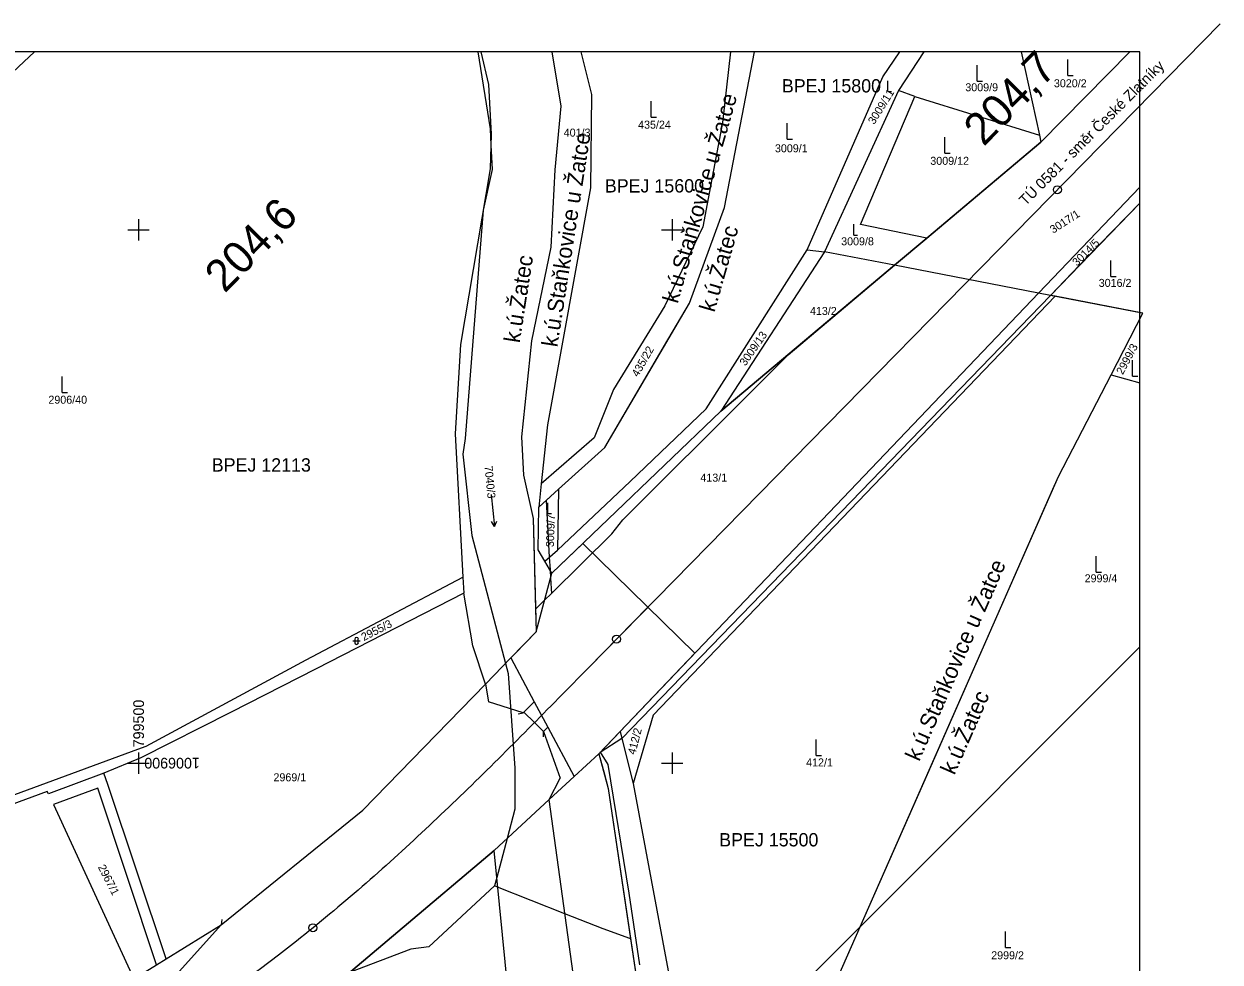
# Model space of a CAD drawing. Extents: x -800194 to -799297, y -1007177 to -1006761.
# Drawn here: x -799521.5 to -799297.3, y -1006937.3 to -1006761.4 of the extents above; entities that cross this region are included whole.
import ezdxf

# ---------------------------------------------------------------- set-up
doc = ezdxf.new("R2010")
doc.units = 0
for name, color, linetype in [('02_Osa_koleje', 7, 'Continuous'), ('_návrh', 7, 'Continuous'), ('_Vrstva 7 - Přesunutá', 7, 'Continuous'), ('BPEJ', 7, 'Continuous'), ('Dočasné zábory', 7, 'Continuous'), ('Legenda 1', 7, 'Continuous'), ('Pozemky SŽDC', 7, 'Continuous'), ('Ramove udaje', 7, 'Continuous'), ('Vrstva 1', 7, 'Continuous'), ('Vrstva 53', 7, 'Continuous'), ('Vrstva 55', 7, 'Continuous'), ('Vrstva 56', 7, 'Continuous'), ('Vrstva 57', 7, 'Continuous'), ('Vrstva 58', 7, 'Continuous'), ('Vrstva 7', 7, 'Continuous')]:
    doc.layers.add(name, color=color, linetype=linetype)

msp = doc.modelspace()

# ---------------------------------------------------------------- linework, layer by layer
at = {"layer": '02_Osa_koleje'}
msp.add_lwpolyline([(-799415.71, -1006882.13), (-799416.41, -1006882.84), (-799417.11, -1006883.55), (-799417.81, -1006884.27), (-799418.51, -1006884.98), (-799419.22, -1006885.7), (-799419.92, -1006886.41), (-799420.62, -1006887.12), (-799421.32, -1006887.84), (-799422.02, -1006888.55), (-799422.72, -1006889.26), (-799423.42, -1006889.97), (-799424.12, -1006890.69), (-799424.83, -1006891.4), (-799425.53, -1006892.11), (-799426.23, -1006892.82), (-799426.94, -1006893.53), (-799427.64, -1006894.24), (-799428.35, -1006894.95), (-799429.05, -1006895.66), (-799429.76, -1006896.36), (-799430.47, -1006897.07), (-799431.17, -1006897.78), (-799431.88, -1006898.48), (-799432.59, -1006899.19), (-799433.3, -1006899.89), (-799434.01, -1006900.6), (-799434.72, -1006901.3), (-799435.44, -1006902), (-799436.15, -1006902.7), (-799436.86, -1006903.4), (-799437.58, -1006904.1), (-799438.29, -1006904.8), (-799439.01, -1006905.5), (-799439.73, -1006906.19), (-799440.45, -1006906.89), (-799441.17, -1006907.58), (-799441.89, -1006908.27), (-799442.61, -1006908.96), (-799443.34, -1006909.65), (-799444.06, -1006910.34), (-799444.79, -1006911.03), (-799445.52, -1006911.72), (-799446.25, -1006912.4), (-799446.98, -1006913.08), (-799447.71, -1006913.77), (-799448.44, -1006914.45), (-799449.18, -1006915.12), (-799449.91, -1006915.8), (-799450.65, -1006916.48), (-799451.39, -1006917.15), (-799452.13, -1006917.82), (-799452.87, -1006918.49), (-799453.61, -1006919.16), (-799454.36, -1006919.83), (-799455.11, -1006920.49), (-799455.85, -1006921.16), (-799456.6, -1006921.82), (-799457.36, -1006922.48), (-799458.11, -1006923.13), (-799458.87, -1006923.79), (-799459.62, -1006924.44), (-799460.38, -1006925.09), (-799461.14, -1006925.74), (-799461.91, -1006926.39), (-799462.67, -1006927.03), (-799463.44, -1006927.68), (-799464.21, -1006928.32), (-799464.98, -1006928.95), (-799465.75, -1006929.59), (-799466.52, -1006930.22), (-799467.3, -1006930.85), (-799468.08, -1006931.48), (-799468.86, -1006932.1), (-799469.64, -1006932.73), (-799470.43, -1006933.35)], dxfattribs=at)
msp.add_arc((-799651.02, -1006703.89), 292, 255.6249, 308.2052, dxfattribs=at)
at = {"layer": '_návrh'}
msp.add_line((-799415.71, -1006882.13), (-799404.56, -1006870.75), dxfattribs=at)
at = {"layer": '_Vrstva 7 - Přesunutá'}
msp.add_circle((-799467.33, -1006930.87), 0.75, dxfattribs=at)
at = {"layer": 'BPEJ'}
msp.add_line((-799329.14, -1006812.3), (-799312.4, -1006795.04), dxfattribs=at)
for points in [[(-799436.44, -1006766.65), (-799434.15, -1006781.08), (-799433.98, -1006784.14), (-799433.73, -1006788.7), (-799435.42, -1006796.33), (-799438.81, -1006839.12), (-799439.24, -1006842.08), (-799437.54, -1006857.33), (-799431.26, -1006881.3), (-799430.76, -1006883.18), (-799429.49, -1006900.97), (-799429.49, -1006908.6), (-799430.96, -1006914.13), (-799432.9, -1006921.45), (-799433.31, -1006923)], [(-799422.55, -1006766.65), (-799420.88, -1006776.85), (-799422, -1006788.79), (-799422.77, -1006803.25), (-799426.4, -1006820.84), (-799428.26, -1006838.83), (-799427.88, -1006846.03), (-799426.08, -1006854.14), (-799425.64, -1006871.12), (-799425.53, -1006875.38), (-799429.53, -1006879.51), (-799430.26, -1006880.27), (-799425.87, -1006888.52), (-799423.34, -1006893.28), (-799418.41, -1006902.53), (-799413.75, -1006898.23), (-799412.83, -1006901.63), (-799411.99, -1006904.75), (-799407.82, -1006932.95)], [(-799423.65, -1006850.78), (-799421.3, -1006848.64), (-799412.65, -1006840.8), (-799400.81, -1006820.64), (-799396.76, -1006813.74), (-799390.24, -1006795.83), (-799384.58, -1006766.65)], [(-799358.35, -1006806.65), (-799352.29, -1006801.56), (-799330.91, -1006783.58), (-799314.24, -1006766.65)], [(-799411.32, -1006857), (-799409.24, -1006854.37), (-799385.18, -1006830.31), (-799378.3, -1006823.42), (-799358.35, -1006806.65)], [(-799329.14, -1006812.3), (-799409.48, -1006895.36), (-799413.52, -1006897.98), (-799413.75, -1006898.23)], [(-799407.82, -1006932.95), (-799406.72, -1006940.36), (-799400.51, -1006971.29), (-799397.01, -1006988.73), (-799388.9, -1006972.36), (-799387.62, -1006968.78), (-799383.1, -1006972.22), (-799364.81, -1006930.69), (-799352.19, -1006902.04), (-799328.67, -1006848.61), (-799327.63, -1006846.25), (-799317.77, -1006827.17), (-799311.83, -1006815.65), (-799311.92, -1006815.63), (-799329.14, -1006812.3)], [(-799423.65, -1006850.78), (-799423.04, -1006861.41)], [(-799422.65, -1006868.17), (-799411.32, -1006857)], [(-799423.04, -1006861.41), (-799422.9, -1006863.76)], [(-799422.9, -1006863.76), (-799422.81, -1006865.33), (-799422.65, -1006868.17)], [(-799425.64, -1006871.12), (-799423.92, -1006869.43), (-799422.65, -1006868.17)], [(-799433.31, -1006923), (-799445.59, -1006934.44), (-799448.98, -1006934.86), (-799460.49, -1006939.26), (-799472.28, -1006943.76), (-799482.03, -1006946.72), (-799486.69, -1006947.15), (-799491.35, -1006948.42), (-799502.85, -1006945.54), (-799507.36, -1006944.41), (-799515.07, -1006942.49), (-799532.02, -1006943.33), (-799567.6, -1006955.2), (-799570.57, -1006956.47), (-799576.08, -1006956.47), (-799584.12, -1006958.16), (-799598.95, -1006964.52), (-799621.99, -1006980.43), (-799662.84, -1007008.64), (-799667.29, -1007011.71), (-799675.63, -1007017.47), (-799679.12, -1007020.67)], [(-799407.82, -1006932.95), (-799407.97, -1006932.89), (-799412.97, -1006931.05), (-799420.12, -1006928.22), (-799432.72, -1006923.23), (-799433.31, -1006923)]]:
    msp.add_lwpolyline(points, dxfattribs=at)
at = {"layer": 'Dočasné zábory'}
msp.add_lwpolyline([(-799406.07, -1006937.82), (-799408.05, -1006924.38), (-799411.99, -1006900.28), (-799413.45, -1006897.92), (-799409.79, -1006894.08), (-799409.48, -1006895.36), (-799407.32, -1006903.81), (-799399.52, -1006945.6)], dxfattribs=at)
at = {"layer": 'Legenda 1'}
msp.add_lwpolyline([(-800193.4, -1007176.65), (-799312.4, -1007176.65), (-799312.4, -1006766.65), (-800193.4, -1006766.65)], close=True, dxfattribs=at)
at = {"layer": 'Pozemky SŽDC'}
msp.add_lwpolyline([(-799559.64, -1006968.48), (-799519.68, -1006952.01), (-799500.87, -1006940.41), (-799496.64, -1006937.8), (-799494.85, -1006936.7), (-799484.52, -1006930.32), (-799457.99, -1006908.8), (-799435, -1006885.17), (-799430.26, -1006880.27), (-799425.53, -1006875.38), (-799422.55, -1006864.36), (-799416.75, -1006858.8), (-799395.76, -1006879.37), (-799413.75, -1006898.23), (-799418.41, -1006902.53), (-799423.07, -1006906.83), (-799433.4, -1006916.39), (-799469.5, -1006946.86), (-799487.22, -1006958.47), (-799495.25, -1006963.74), (-799521.98, -1006977.8)], dxfattribs=at)
at = {"layer": 'Ramove udaje'}
for p, q in [((-799502, -1006800), (-799500, -1006800)), ((-799500, -1006798), (-799500, -1006802)), ((-799500, -1006800), (-799498, -1006800)), ((-799402, -1006800), (-799400, -1006800)), ((-799400, -1006798), (-799400, -1006802)), ((-799400, -1006800), (-799398, -1006800)), ((-799500, -1006898), (-799500, -1006902)), ((-799400, -1006898), (-799400, -1006902)), ((-799502, -1006900), (-799500, -1006900)), ((-799500, -1006900), (-799498, -1006900)), ((-799402, -1006900), (-799400, -1006900)), ((-799400, -1006900), (-799398, -1006900))]:
    msp.add_line(p, q, dxfattribs=at)
at = {"layer": 'Vrstva 1'}
msp.add_line((-799415.71, -1006882.13), (-799297.34, -1006761.4), dxfattribs=at)
at = {"layer": 'Vrstva 53'}
for points in [[(-799559.64, -1006968.48), (-799519.68, -1006952.01), (-799500.87, -1006940.41), (-799496.64, -1006937.8), (-799494.85, -1006936.7), (-799484.52, -1006930.32), (-799457.99, -1006908.8), (-799435, -1006885.17), (-799430.26, -1006880.27), (-799425.53, -1006875.38), (-799422.55, -1006864.36), (-799390.88, -1006834), (-799358.35, -1006806.65), (-799352.29, -1006801.56), (-799330.91, -1006783.58), (-799314.24, -1006766.65)], [(-799312.4, -1006791.98), (-799331.37, -1006811.87), (-799413.75, -1006898.23), (-799418.41, -1006902.53), (-799423.07, -1006906.83), (-799433.4, -1006916.39), (-799469.5, -1006946.86), (-799487.22, -1006958.47), (-799495.25, -1006963.74), (-799521.98, -1006977.8)]]:
    msp.add_lwpolyline(points, dxfattribs=at)
at = {"layer": 'Vrstva 55'}
for p, q in [((-799352.83, -1006766.65), (-799357.58, -1006773.87)), ((-799334.64, -1006766.65), (-799331.2, -1006782.25)), ((-799314.24, -1006766.65), (-799330.91, -1006783.58)), ((-799357.58, -1006773.87), (-799371.45, -1006804.11)), ((-799354.52, -1006775), (-799357.58, -1006773.87)), ((-799354.52, -1006775), (-799331.2, -1006782.25)), ((-799330.91, -1006783.58), (-799352.29, -1006801.56)), ((-799331.2, -1006782.25), (-799330.91, -1006783.58)), ((-799352.29, -1006801.56), (-799358.35, -1006806.65)), ((-799371.45, -1006804.11), (-799390.88, -1006834)), ((-799374.69, -1006803.75), (-799371.45, -1006804.11)), ((-799358.35, -1006806.65), (-799371.45, -1006804.11)), ((-799358.35, -1006806.65), (-799390.88, -1006834)), ((-799331.37, -1006811.87), (-799358.35, -1006806.65)), ((-799413.75, -1006898.23), (-799331.37, -1006811.87)), ((-799329.14, -1006812.3), (-799331.37, -1006811.87)), ((-799328.26, -1006812.47), (-799329.14, -1006812.3)), ((-799311.83, -1006815.65), (-799328.26, -1006812.47)), ((-799317.77, -1006827.17), (-799311.83, -1006815.65)), ((-799317.77, -1006827.17), (-799312.4, -1006828.72)), ((-799390.88, -1006834), (-799422.55, -1006864.36)), ((-799424.54, -1006847.65), (-799425, -1006852)), ((-799425, -1006852), (-799421.3, -1006848.64)), ((-799421.3, -1006848.64), (-799421.51, -1006860.09)), ((-799423.86, -1006862.12), (-799421.51, -1006860.09)), ((-799422.55, -1006864.36), (-799423.86, -1006862.12)), ((-799439.23, -1006865.13), (-799439.06, -1006868.14)), ((-799425.53, -1006875.38), (-799422.55, -1006864.36)), ((-799425.53, -1006875.38), (-799430.26, -1006880.27)), ((-799364.81, -1006930.69), (-799312.4, -1006878.2)), ((-799430.26, -1006880.27), (-799435, -1006885.17)), ((-799430.26, -1006880.27), (-799425.87, -1006888.52)), ((-799425.87, -1006888.52), (-799423.34, -1006893.28)), ((-799423.34, -1006893.28), (-799418.41, -1006902.53)), ((-799418.41, -1006902.53), (-799413.75, -1006898.23)), ((-799423.07, -1006906.83), (-799418.41, -1006902.53)), ((-799433.4, -1006916.39), (-799423.07, -1006906.83)), ((-799424.1, -1007009.73), (-799433.4, -1006916.39)), ((-799393.3, -1006959.22), (-799364.81, -1006930.69)), ((-799383.1, -1006972.22), (-799364.81, -1006930.69)), ((-799496.64, -1006937.8), (-799494.85, -1006936.7))]:
    msp.add_line(p, q, dxfattribs=at)
for points in [[(-799605.96, -1006806.87), (-799585.51, -1006812.81), (-799578.02, -1006814.17), (-799567.46, -1006810.26), (-799560.01, -1006804.4), (-799538.65, -1006784.55), (-799525.56, -1006772.33), (-799519.54, -1006766.65)], [(-799435.89, -1006766.65), (-799434.45, -1006772.74), (-799433.92, -1006782.05), (-799434.12, -1006788.57), (-799439.66, -1006821.53), (-799440.71, -1006838.23), (-799439.23, -1006865.13)], [(-799422.55, -1006766.65), (-799420.88, -1006776.85), (-799422, -1006788.79), (-799422.77, -1006803.25), (-799426.4, -1006820.84), (-799428.26, -1006838.83), (-799427.88, -1006846.03), (-799426.08, -1006854.14), (-799425.53, -1006875.38)], [(-799417.14, -1006766.65), (-799415.15, -1006774.66), (-799415.3, -1006792.16), (-799423.37, -1006836.59), (-799424.54, -1006847.65)], [(-799389.07, -1006766.65), (-799390.61, -1006779.89), (-799394.27, -1006799.42), (-799401.41, -1006814.24), (-799411, -1006829.93), (-799414.66, -1006839), (-799424.54, -1006847.65)], [(-799421.3, -1006848.64), (-799412.65, -1006840.8), (-799396.76, -1006813.74), (-799390.24, -1006795.83), (-799384.58, -1006766.65)], [(-799374.69, -1006803.75), (-799360.51, -1006771.31), (-799357.35, -1006766.65)], [(-799352.29, -1006801.56), (-799364.7, -1006799), (-799354.52, -1006775)], [(-799312.4, -1006791.98), (-799331.37, -1006811.87)], [(-799312.4, -1006795.04), (-799322.34, -1006805.27), (-799329.14, -1006812.3)], [(-799421.51, -1006860.09), (-799407.9, -1006847.2), (-799393.66, -1006833.58), (-799374.69, -1006803.75)], [(-799329.14, -1006812.3), (-799409.48, -1006895.36), (-799407.32, -1006903.81)], [(-799328.26, -1006812.47), (-799403.59, -1006891), (-799407.32, -1006903.81)], [(-799364.81, -1006930.69), (-799327.63, -1006846.25), (-799317.77, -1006827.17)], [(-799423.86, -1006862.12), (-799425.1, -1006860), (-799425, -1006852)], [(-799498.58, -1006896.8), (-799468.62, -1006880.61), (-799439.23, -1006865.13)], [(-799439.06, -1006868.14), (-799466.75, -1006882.3), (-799482.8, -1006890.48), (-799499.57, -1006898.99), (-799506.49, -1006901.85)], [(-799435, -1006885.17), (-799437.37, -1006878.01), (-799439.06, -1006868.14)], [(-799494.85, -1006936.7), (-799484.52, -1006930.32), (-799457.99, -1006908.8), (-799435, -1006885.17)], [(-799586.79, -1006927.02), (-799561.07, -1006919.79), (-799500.17, -1006897.39), (-799498.58, -1006896.8)], [(-799413.75, -1006898.23), (-799411.99, -1006904.75), (-799406.72, -1006940.36), (-799397.01, -1006988.73)], [(-799506.49, -1006901.85), (-799516.91, -1006905.73), (-799517.11, -1006905.3), (-799557.12, -1006920.07)], [(-799494.85, -1006936.7), (-799505.77, -1006904), (-799506.49, -1006901.85)], [(-799496.64, -1006937.8), (-799507.65, -1006904.69), (-799515.98, -1006907.74), (-799500.87, -1006940.41)], [(-799407.32, -1006903.81), (-799399.52, -1006945.6), (-799393.3, -1006959.22)], [(-799410.89, -1007000.14), (-799412.5, -1006983.38), (-799423.07, -1006906.83)], [(-799487.22, -1006958.47), (-799469.5, -1006946.86), (-799433.4, -1006916.39)]]:
    msp.add_lwpolyline(points, dxfattribs=at)
at = {"layer": 'Vrstva 56'}
for p, q in [((-799435, -1006885.17), (-799434.41, -1006888.48)), ((-799427.92, -1006890.55), (-799434.41, -1006888.48)), ((-799427.79, -1006890.42), (-799425.87, -1006888.52)), ((-799428.9, -1006890.76), (-799427.92, -1006890.55)), ((-799427.92, -1006890.55), (-799427.79, -1006890.42)), ((-799427.79, -1006890.42), (-799425.84, -1006892.36)), ((-799425.84, -1006892.36), (-799424.13, -1006894.07)), ((-799423.34, -1006893.28), (-799424.13, -1006894.07)), ((-799424.11, -1006895.07), (-799424.13, -1006894.07)), ((-799424.13, -1006894.07), (-799421, -1006902.84)), ((-799423.07, -1006906.83), (-799421, -1006902.84)), ((-799484.42, -1006929.33), (-799484.52, -1006930.32)), ((-799484.52, -1006930.32), (-799492.32, -1006939.01))]:
    msp.add_line(p, q, dxfattribs=at)
at = {"layer": 'Vrstva 58'}
for p, q in [((-799325.85, -1006771.07), (-799325.85, -1006768.07)), ((-799342.86, -1006772.12), (-799342.86, -1006769.12)), ((-799359.6, -1006774.08), (-799359.6, -1006772.07)), ((-799342.86, -1006772.12), (-799341.85, -1006772.12)), ((-799325.85, -1006771.07), (-799324.85, -1006771.07)), ((-799359.6, -1006774.08), (-799358.93, -1006774.08)), ((-799403.93, -1006778.9), (-799403.93, -1006775.9)), ((-799403.93, -1006778.9), (-799402.93, -1006778.9)), ((-799378.46, -1006783.03), (-799378.46, -1006780.03)), ((-799378.46, -1006783.03), (-799377.46, -1006783.03)), ((-799348.92, -1006785.62), (-799348.92, -1006782.62)), ((-799348.92, -1006785.62), (-799347.92, -1006785.62)), ((-799365.97, -1006800.98), (-799365.97, -1006798.97)), ((-799365.97, -1006800.98), (-799365.3, -1006800.98)), ((-799317.81, -1006808.74), (-799317.81, -1006805.74)), ((-799317.81, -1006808.74), (-799316.81, -1006808.74)), ((-799313.77, -1006827.47), (-799313.77, -1006824.47)), ((-799514.35, -1006830.52), (-799514.35, -1006827.52)), ((-799313.77, -1006827.47), (-799312.77, -1006827.47)), ((-799514.35, -1006830.52), (-799513.35, -1006830.52)), ((-799433.93, -1006849.66), (-799433.29, -1006855.63)), ((-799423.31, -1006853.2), (-799423.31, -1006851.19)), ((-799423.31, -1006853.2), (-799422.64, -1006853.2)), ((-799433.29, -1006855.63), (-799433.89, -1006854.71)), ((-799433.29, -1006855.63), (-799432.9, -1006854.6)), ((-799320.53, -1006864.22), (-799320.53, -1006861.22)), ((-799320.53, -1006864.22), (-799319.53, -1006864.22)), ((-799459.83, -1006877.08), (-799458.49, -1006877.08)), ((-799459.49, -1006876.74), (-799459.49, -1006877.42)), ((-799458.83, -1006877.42), (-799458.83, -1006876.74)), ((-799373.05, -1006898.58), (-799373.05, -1006895.58)), ((-799373.05, -1006898.58), (-799372.05, -1006898.58)), ((-799337.58, -1006934.56), (-799337.58, -1006931.56)), ((-799337.58, -1006934.56), (-799336.58, -1006934.56))]:
    msp.add_line(p, q, dxfattribs=at)
for centre, start, end in [((-799459.16, -1006876.75), 0, 180), ((-799459.16, -1006877.42), 180, 359.9879)]:
    msp.add_arc(centre, 0.335, start, end, dxfattribs=at)
at = {"layer": 'Vrstva 7'}
for centre in [(-799327.82, -1006792.49), (-799410.44, -1006876.75)]:
    msp.add_circle(centre, 0.75, dxfattribs=at)

# ---------------------------------------------------------------- texts
at = {"layer": '02_Osa_koleje'}
msp.add_text('TÚ 0581 - směr České Zlatníky', height=2, rotation=45.0156, dxfattribs=at).set_placement((-799333.79, -1006795.62))
at = {"layer": 'BPEJ'}
for s, p in [('BPEJ 15800', (-799379.46, -1006774.26)), ('BPEJ 15600', (-799412.63, -1006793.01)), ('BPEJ 12113', (-799486.3, -1006845.34)), ('BPEJ 15500', (-799391.2, -1006915.61))]:
    msp.add_text(s, height=2.5, dxfattribs=at).set_placement(p)
at = {"layer": 'Ramove udaje'}
for s, rotation, p in [('    799500', 90, (-799499, -1006900)), ('1006900    ', 180, (-799488.53, -1006899))]:
    msp.add_text(s, height=2, rotation=rotation, dxfattribs=at).set_placement(p)
at = {"layer": 'Vrstva 55'}
for s, rotation, p in [('k.ú.Staňkovice u Žatce', 73.9881, (-799398.99, -1006813.95)), ('k.ú.Staňkovice u Žatce', 81.1486, (-799421.54, -1006822.1)), ('k.ú.Žatec', 73.9881, (-799392.1, -1006815.59)), ('k.ú.Žatec', 81.1486, (-799428.59, -1006821.32)), ('k.ú.Staňkovice u Žatce', 66.2843, (-799353.73, -1006899.81)), ('k.ú.Žatec', 66.2843, (-799347.12, -1006902.36))]:
    msp.add_text(s, height=3, rotation=rotation, dxfattribs=at).set_placement(p)
at = {"layer": 'Vrstva 57'}
for s, p in [('3009/9', (-799345.08, -1006774.03)), ('3020/2', (-799328.48, -1006773.28)), ('435/24', (-799406.4, -1006781.04)), ('401/3', (-799420.34, -1006782.53)), ('3009/1', (-799380.76, -1006785.47)), ('3009/12', (-799351.64, -1006787.82)), ('3009/8', (-799368.35, -1006802.91)), ('3016/2', (-799320.08, -1006810.71)), ('413/2', (-799374.19, -1006815.97)), ('2906/40', (-799516.91, -1006832.61)), ('413/1', (-799394.73, -1006847.22)), ('2999/4', (-799322.72, -1006866.09)), ('412/1', (-799374.91, -1006900.61)), ('2969/1', (-799474.73, -1006903.4)), ('2999/2', (-799340.23, -1006936.77))]:
    msp.add_text(s, height=1.5, dxfattribs=at).set_placement(p)
for s, rotation, p in [('3009/11', 58, (-799362.16, -1006780.37)), ('3017/1', 33, (-799328.61, -1006800.75)), ('3014/5', 45, (-799324.15, -1006806.92)), ('3009/13', 55, (-799386.29, -1006825.65)), ('435/22', 60.1157, (-799406.42, -1006827.7)), ('2999/3', 61.8819, (-799315.57, -1006827.28)), ('7040/3', 275.5855, (-799435.19, -1006844.32)), ('3009/7', 88, (-799422.19, -1006859.5)), ('2955/3', 27, (-799457.82, -1006877.14)), ('412/2', 75.4361, (-799406.94, -1006898.5)), ('2967/1', 297, (-799507.67, -1006919.48))]:
    msp.add_text(s, height=1.5, rotation=rotation, dxfattribs=at).set_placement(p)
at = {"layer": 'Vrstva 7'}
for s, p in [('204,7', (-799341.65, -1006784.52)), ('204,6', (-799483.87, -1006812.02))]:
    msp.add_text(s, height=6, rotation=45.5634, dxfattribs=at).set_placement(p)

doc.saveas('drawing.dxf')
